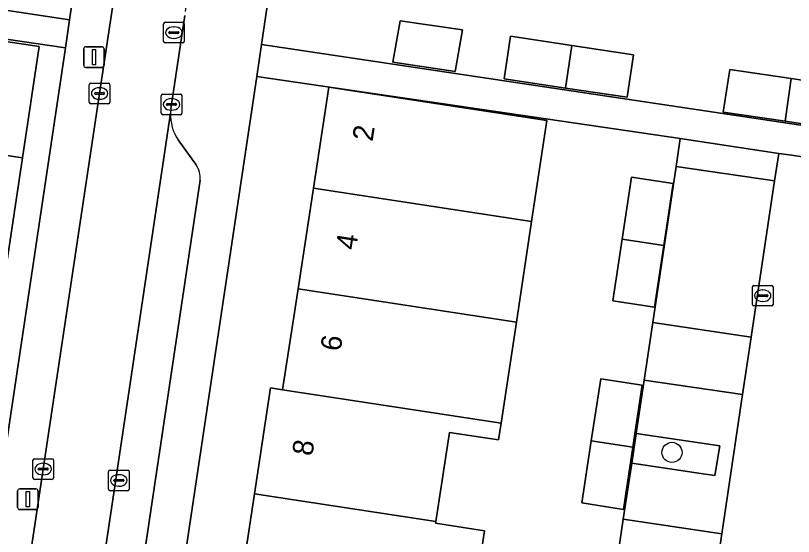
# Model space of a CAD drawing. Extents: x 164148 to 165261, y 382513 to 383432.
# Drawn here: x 164310.2 to 164347.95, y 382822.75 to 382848.02 of the extents above; entities that cross this region are included whole.
import ezdxf

# ---------------------------------------------------------------- set-up
doc = ezdxf.new("R2010")
doc.units = 0
for name, color, linetype in [('IMGEO_Boom', 7, 'Continuous'), ('IMGEO_Erf', 7, 'Continuous'), ('IMGEO_Groenvoorziening', 7, 'Continuous'), ('IMGEO_Kolk', 7, 'Continuous'), ('IMGEO_Lichtmast', 7, 'Continuous'), ('IMGEO_Pand', 7, 'Continuous'), ('IMGEO_Pand_nummerreeks', 7, 'Continuous'), ('IMGEO_Parkeervlak_open', 7, 'Continuous'), ('IMGEO_Rijbaan_lokaal_open', 7, 'Continuous'), ('IMGEO_Rioolput', 7, 'Continuous'), ('IMGEO_Voetpad_open', 7, 'Continuous')]:
    doc.layers.add(name, color=color, linetype=linetype)

msp = doc.modelspace()

# ---------------------------------------------------------------- linework, layer by layer
at = {"layer": 'IMGEO_Boom'}
msp.add_circle((164342.059, 382826.829), 0.489, dxfattribs=at)
at = {"layer": 'IMGEO_Erf'}
for points in [[(164315.881, 382868.253), (164315.414, 382868.927), (164260.822, 382877.103), (164260.194, 382876.574), (164257.168, 382856.277), (164287.898, 382851.603), (164312.82, 382847.812)], [(164380.889, 382859.124), (164325.776, 382867.343), (164325.126, 382866.898), (164322.133, 382846.618), (164350.25, 382842.417), (164378.331, 382838.195), (164381.369, 382858.602)], [(164312.617, 382846.453), (164292.449, 382849.423), (164292.087, 382847.018), (164291.688, 382844.368), (164291.474, 382842.945), (164291.038, 382840.051), (164290.538, 382836.727), (164289.415, 382829.267), (164288.932, 382826.06), (164287.807, 382818.59), (164287.325, 382815.39), (164286.852, 382812.248), (164286.634, 382810.8), (164286.198, 382807.902), (164285.91, 382805.985), (164306.097, 382802.914)], [(164295.742, 382810.175), (164296.551, 382815.581), (164297.361, 382820.987), (164298.17, 382826.393), (164298.979, 382831.798), (164299.789, 382837.204), (164300.598, 382842.61), (164301.407, 382848.016), (164311.351, 382846.529), (164310.54, 382841.122), (164309.73, 382835.716), (164308.919, 382830.31), (164308.108, 382824.905), (164307.298, 382819.499), (164306.487, 382814.093), (164305.677, 382808.688), (164304.859, 382803.235), (164294.933, 382804.769)], [(164331.884, 382847.33), (164331.535, 382845.31), (164328.504, 382845.765), (164328.874, 382847.776)], [(164337.206, 382846.568), (164340.195, 382846.118), (164339.885, 382844.057), (164336.896, 382844.506), (164333.907, 382844.956), (164334.217, 382847.017)], [(164350.836, 382844.524), (164350.517, 382842.454), (164347.545, 382842.897), (164344.545, 382843.344), (164344.866, 382845.407), (164347.851, 382844.966)], [(164339.185, 382834.177), (164339.639, 382837.178), (164340.095, 382840.186), (164342.122, 382839.869), (164341.664, 382836.869), (164341.205, 382833.868)], [(164340.618, 382830.085), (164340.165, 382827.081), (164339.709, 382824.062), (164337.69, 382824.381), (164338.145, 382827.387), (164338.599, 382830.392)]]:
    msp.add_lwpolyline(points, close=True, dxfattribs=at)
for points in [[(164336.319, 382801.003), (164336.717, 382803.665), (164337.854, 382811.264), (164338.195, 382813.542), (164339.299, 382820.92), (164339.698, 382823.586), (164340.106, 382826.312), (164340.321, 382827.745), (164340.709, 382830.337), (164341.126, 382833.13), (164342.26, 382840.703), (164342.463, 382842.062), (164321.904, 382845.071), (164308.618, 382756.371)], [(164321.014, 382819.693), (164321.797, 382824.824), (164322.58, 382829.954), (164323.163, 382829.865), (164323.91, 382834.759), (164324.656, 382839.654), (164325.403, 382844.548), (164335.987, 382842.933), (164335.246, 382838.038), (164334.505, 382833.143), (164333.764, 382828.247), (164333.642, 382827.438), (164331.262, 382827.801), (164330.603, 382823.48), (164330.589, 382823.386), (164332.963, 382823.024), (164332.195, 382817.987)]]:
    msp.add_lwpolyline(points, dxfattribs=at)
at = {"layer": 'IMGEO_Groenvoorziening'}
msp.add_lwpolyline([(164340.321, 382827.745), (164340.106, 382826.312), (164343.459, 382825.804), (164344.145, 382825.7), (164344.375, 382827.141)], close=True, dxfattribs=at)
at = {"layer": 'IMGEO_Kolk'}
for p, q in [((164313.777, 382843.818), (164313.777, 382844.67)), ((164313.852, 382844.744), (164314.704, 382844.744)), ((164314.778, 382844.67), (164314.778, 382843.818)), ((164314.036, 382844.238), (164314.036, 382844.25)), ((164314.079, 382844.287), (164314.477, 382844.287)), ((164314.265, 382844.524), (164314.29, 382844.524)), ((164314.52, 382844.25), (164314.52, 382844.238)), ((164314.474, 382844.201), (164314.076, 382844.201)), ((164314.288, 382843.964), (164314.263, 382843.964)), ((164317.27, 382843.288), (164317.27, 382844.14)), ((164317.345, 382844.214), (164318.197, 382844.214)), ((164317.758, 382843.994), (164317.783, 382843.994)), ((164318.271, 382844.14), (164318.271, 382843.288)), ((164314.704, 382843.744), (164313.852, 382843.744)), ((164317.529, 382843.708), (164317.529, 382843.72)), ((164317.967, 382843.671), (164317.569, 382843.671)), ((164317.572, 382843.757), (164317.97, 382843.757)), ((164318.013, 382843.72), (164318.013, 382843.708)), ((164318.197, 382843.214), (164317.345, 382843.214)), ((164317.781, 382843.434), (164317.756, 382843.434)), ((164345.962, 382834.006), (164345.962, 382834.858)), ((164346.037, 382834.932), (164346.889, 382834.932)), ((164346.963, 382834.858), (164346.963, 382834.006)), ((164346.221, 382834.426), (164346.221, 382834.438)), ((164346.264, 382834.475), (164346.662, 382834.475)), ((164346.45, 382834.712), (164346.475, 382834.712)), ((164346.705, 382834.438), (164346.705, 382834.426)), ((164346.659, 382834.389), (164346.261, 382834.389)), ((164346.473, 382834.152), (164346.448, 382834.152)), ((164346.889, 382833.932), (164346.037, 382833.932)), ((164311.115, 382826.519), (164311.967, 382826.519)), ((164311.04, 382825.593), (164311.04, 382826.445)), ((164311.528, 382826.299), (164311.553, 382826.299)), ((164312.041, 382826.445), (164312.041, 382825.593)), ((164311.299, 382826.013), (164311.299, 382826.025)), ((164311.737, 382825.976), (164311.339, 382825.976)), ((164311.342, 382826.062), (164311.74, 382826.062)), ((164311.551, 382825.739), (164311.526, 382825.739)), ((164311.783, 382826.025), (164311.783, 382826.013)), ((164314.71, 382825.041), (164314.71, 382825.893)), ((164314.785, 382825.967), (164315.637, 382825.967)), ((164315.198, 382825.747), (164315.223, 382825.747)), ((164315.711, 382825.893), (164315.711, 382825.041)), ((164311.967, 382825.519), (164311.115, 382825.519)), ((164314.969, 382825.461), (164314.969, 382825.473)), ((164315.407, 382825.424), (164315.009, 382825.424)), ((164315.012, 382825.51), (164315.41, 382825.51)), ((164315.453, 382825.473), (164315.453, 382825.461)), ((164315.221, 382825.187), (164315.196, 382825.187)), ((164315.637, 382824.967), (164314.785, 382824.967))]:
    msp.add_line(p, q, dxfattribs=at)
for points in [[(164313.777, 382843.818), (164313.777, 382844.67)], [(164313.852, 382844.744), (164314.704, 382844.744)], [(164314.778, 382844.67), (164314.778, 382843.818)], [(164317.27, 382843.288), (164317.27, 382844.14)], [(164317.345, 382844.214), (164318.197, 382844.214)], [(164318.271, 382844.14), (164318.271, 382843.288)], [(164314.704, 382843.744), (164313.852, 382843.744)], [(164318.197, 382843.214), (164317.345, 382843.214)], [(164345.962, 382834.006), (164345.962, 382834.858)], [(164346.037, 382834.932), (164346.889, 382834.932)], [(164346.963, 382834.858), (164346.963, 382834.006)], [(164346.889, 382833.932), (164346.037, 382833.932)], [(164311.115, 382826.519), (164311.967, 382826.519)], [(164311.04, 382825.593), (164311.04, 382826.445)], [(164312.041, 382826.445), (164312.041, 382825.593)], [(164314.71, 382825.041), (164314.71, 382825.893)], [(164314.785, 382825.967), (164315.637, 382825.967)], [(164315.711, 382825.893), (164315.711, 382825.041)], [(164311.967, 382825.519), (164311.115, 382825.519)], [(164315.637, 382824.967), (164314.785, 382824.967)]]:
    msp.add_lwpolyline(points, dxfattribs=at)
for centre, radius, start, end in [((164313.854, 382844.668), 0.0765, 91.552, 178.448), ((164313.854, 382844.668), 0.0765, 91.552, 178.448), ((164314.702, 382844.668), 0.0765, 1.552, 88.448), ((164314.702, 382844.668), 0.0765, 1.552, 88.448), ((164314.076, 382844.247), 0.0403, 85.8775, 175.7526), ((164314.073, 382844.237), 0.0366, 178.938, 274.7102), ((164314.477, 382844.244), 0.043, 264.8664, 352.4533), ((164314.481, 382844.249), 0.0386, 1.7309, 96.639), ((164317.347, 382844.138), 0.0765, 91.552, 178.448), ((164317.347, 382844.138), 0.0765, 91.552, 178.448), ((164318.195, 382844.138), 0.0765, 1.552, 88.448), ((164318.195, 382844.138), 0.0765, 1.552, 88.448), ((164313.854, 382843.82), 0.0765, 181.552, 268.448), ((164313.854, 382843.82), 0.0765, 181.552, 268.448), ((164314.702, 382843.82), 0.0765, 271.552, 358.448), ((164314.702, 382843.82), 0.0765, 271.552, 358.448), ((164317.569, 382843.717), 0.0403, 85.8775, 175.7526), ((164317.566, 382843.707), 0.0366, 178.938, 274.7102), ((164317.97, 382843.714), 0.043, 264.8664, 352.4533), ((164317.974, 382843.719), 0.0386, 1.7309, 96.639), ((164317.347, 382843.29), 0.0765, 181.552, 268.448), ((164317.347, 382843.29), 0.0765, 181.552, 268.448), ((164318.195, 382843.29), 0.0765, 271.552, 358.448), ((164318.195, 382843.29), 0.0765, 271.552, 358.448), ((164346.039, 382834.856), 0.0765, 91.552, 178.448), ((164346.039, 382834.856), 0.0765, 91.552, 178.448), ((164346.887, 382834.856), 0.0765, 1.552, 88.448), ((164346.887, 382834.856), 0.0765, 1.552, 88.448), ((164346.261, 382834.435), 0.0403, 85.8775, 175.7526), ((164346.258, 382834.425), 0.0366, 178.938, 274.7102), ((164346.662, 382834.432), 0.043, 264.8664, 352.4533), ((164346.666, 382834.437), 0.0386, 1.7309, 96.639), ((164346.039, 382834.008), 0.0765, 181.552, 268.448), ((164346.039, 382834.008), 0.0765, 181.552, 268.448), ((164346.887, 382834.008), 0.0765, 271.552, 358.448), ((164346.887, 382834.008), 0.0765, 271.552, 358.448), ((164311.117, 382826.443), 0.0765, 91.552, 178.448), ((164311.117, 382826.443), 0.0765, 91.552, 178.448), ((164311.965, 382826.443), 0.0765, 1.552, 88.448), ((164311.965, 382826.443), 0.0765, 1.552, 88.448), ((164311.339, 382826.022), 0.0403, 85.8775, 175.7526), ((164311.336, 382826.012), 0.0366, 178.938, 274.7102), ((164311.74, 382826.019), 0.043, 264.8664, 352.4533), ((164311.744, 382826.024), 0.0386, 1.7309, 96.639), ((164314.787, 382825.891), 0.0765, 91.552, 178.448), ((164314.787, 382825.891), 0.0765, 91.552, 178.448), ((164315.635, 382825.891), 0.0765, 1.552, 88.448), ((164315.635, 382825.891), 0.0765, 1.552, 88.448), ((164311.117, 382825.595), 0.0765, 181.552, 268.448), ((164311.117, 382825.595), 0.0765, 181.552, 268.448), ((164311.965, 382825.595), 0.0765, 271.552, 358.448), ((164311.965, 382825.595), 0.0765, 271.552, 358.448), ((164315.009, 382825.47), 0.0403, 85.8775, 175.7526), ((164315.006, 382825.46), 0.0366, 178.938, 274.7102), ((164315.41, 382825.467), 0.043, 264.8664, 352.4533), ((164315.414, 382825.472), 0.0386, 1.7309, 96.639), ((164314.787, 382825.043), 0.0765, 181.552, 268.448), ((164314.787, 382825.043), 0.0765, 181.552, 268.448), ((164315.635, 382825.043), 0.0765, 271.552, 358.448), ((164315.635, 382825.043), 0.0765, 271.552, 358.448)]:
    msp.add_arc(centre, radius, start, end, dxfattribs=at)
for centre, major_axis, ratio, start_param, end_param in [((164314.264, 382844.244), (-0.387, 0.002), 0.722429, 4.712389, 7.853982), ((164314.289, 382844.244), (-0.39, 0.002), 0.717154, 1.570796, 4.712389), ((164317.757, 382843.714), (-0.387, 0.002), 0.722429, 4.712389, 7.853982), ((164317.782, 382843.714), (-0.39, 0.002), 0.717154, 1.570796, 4.712389), ((164346.449, 382834.432), (-0.387, 0.002), 0.722429, 4.712389, 7.853982), ((164346.474, 382834.432), (-0.39, 0.002), 0.717154, 1.570796, 4.712389), ((164311.527, 382826.019), (-0.387, 0.002), 0.722429, 4.712389, 7.853982), ((164311.552, 382826.019), (-0.39, 0.002), 0.717154, 1.570796, 4.712389), ((164315.197, 382825.467), (-0.387, 0.002), 0.722429, 4.712389, 7.853982), ((164315.222, 382825.467), (-0.39, 0.002), 0.717154, 1.570796, 4.712389)]:
    msp.add_ellipse(centre, major_axis=major_axis, ratio=ratio, start_param=start_param, end_param=end_param, dxfattribs=at)
at = {"layer": 'IMGEO_Lichtmast'}
for p, q in [((164313.607, 382846.51), (164314.397, 382846.51)), ((164314.397, 382846.51), (164313.607, 382846.51)), ((164313.507, 382845.61), (164313.507, 382846.41)), ((164313.507, 382846.41), (164313.507, 382845.61)), ((164314.497, 382846.41), (164314.497, 382845.61)), ((164314.497, 382845.61), (164314.497, 382846.41)), ((164314.397, 382845.51), (164313.607, 382845.51)), ((164313.607, 382845.51), (164314.397, 382845.51)), ((164310.401, 382825.056), (164311.191, 382825.056)), ((164311.191, 382825.056), (164310.401, 382825.056)), ((164310.301, 382824.156), (164310.301, 382824.956)), ((164310.301, 382824.956), (164310.301, 382824.156)), ((164311.291, 382824.956), (164311.291, 382824.156)), ((164311.291, 382824.156), (164311.291, 382824.956)), ((164311.191, 382824.056), (164310.401, 382824.056)), ((164310.401, 382824.056), (164311.191, 382824.056))]:
    msp.add_line(p, q, dxfattribs=at)
for points in [[(164313.927, 382846.385), (164314.077, 382846.385), (164314.077, 382845.635), (164313.927, 382845.635), (164313.927, 382846.385)], [(164310.721, 382824.931), (164310.871, 382824.931), (164310.871, 382824.181), (164310.721, 382824.181), (164310.721, 382824.931)]]:
    msp.add_lwpolyline(points, dxfattribs=at)
for centre, start, end in [((164313.607, 382846.41), 90, 180), ((164313.607, 382846.41), 90, 180), ((164314.397, 382846.41), 0, 90), ((164314.397, 382846.41), 360, 90), ((164313.607, 382845.61), 180, 270), ((164313.607, 382845.61), 180, 270), ((164314.397, 382845.61), 270, 0), ((164314.397, 382845.61), 270, 0), ((164310.401, 382824.956), 90, 180), ((164310.401, 382824.956), 90, 180), ((164311.191, 382824.956), 0, 90), ((164311.191, 382824.956), 360, 90), ((164310.401, 382824.156), 180, 270), ((164310.401, 382824.156), 180, 270), ((164311.191, 382824.156), 270, 0), ((164311.191, 382824.156), 270, 0)]:
    msp.add_arc(centre, 0.1, start, end, dxfattribs=at)
at = {"layer": 'IMGEO_Pand'}
for points in [[(164301.407, 382848.016), (164300.598, 382842.61), (164310.54, 382841.122), (164311.351, 382846.529)], [(164331.884, 382847.33), (164328.874, 382847.776), (164328.504, 382845.765), (164331.535, 382845.31)], [(164337.206, 382846.568), (164334.217, 382847.017), (164333.907, 382844.956), (164336.896, 382844.506)], [(164340.195, 382846.118), (164337.206, 382846.568), (164336.896, 382844.506), (164339.885, 382844.057)], [(164347.851, 382844.966), (164344.866, 382845.407), (164344.545, 382843.344), (164347.545, 382842.897)], [(164350.836, 382844.524), (164347.851, 382844.966), (164347.545, 382842.897), (164350.517, 382842.454)], [(164335.987, 382842.933), (164325.403, 382844.548), (164324.656, 382839.654), (164335.246, 382838.038)], [(164310.54, 382841.122), (164300.598, 382842.61), (164299.789, 382837.204), (164309.73, 382835.716)], [(164342.122, 382839.869), (164340.095, 382840.186), (164339.639, 382837.178), (164341.664, 382836.869)], [(164335.246, 382838.038), (164324.656, 382839.654), (164323.91, 382834.759), (164334.505, 382833.143)], [(164341.664, 382836.869), (164339.639, 382837.178), (164339.185, 382834.177), (164341.205, 382833.868)], [(164334.505, 382833.143), (164323.91, 382834.759), (164323.163, 382829.865), (164333.764, 382828.247)], [(164338.599, 382830.392), (164338.145, 382827.387), (164340.165, 382827.081), (164340.618, 382830.085)], [(164331.262, 382827.801), (164333.642, 382827.438), (164333.764, 382828.247), (164323.163, 382829.865), (164322.58, 382829.954), (164321.797, 382824.824), (164330.603, 382823.48)], [(164340.165, 382827.081), (164338.145, 382827.387), (164337.69, 382824.381), (164339.709, 382824.062)], [(164332.963, 382823.024), (164330.589, 382823.386), (164330.603, 382823.48), (164321.797, 382824.824), (164321.014, 382819.693), (164321.607, 382819.602), (164332.195, 382817.987)]]:
    msp.add_lwpolyline(points, close=True, dxfattribs=at)
at = {"layer": 'IMGEO_Parkeervlak_open'}
for points in [[(164317.721, 382843.296), (164305.588, 382762.12)], [(164318.963, 382840.775), (164318.093, 382841.994)], [(164307.907, 382764.872), (164319.154, 382840.039)]]:
    msp.add_lwpolyline(points, dxfattribs=at)
for points in [[(164347.039, 382839.997), (164342.26, 382840.703), (164341.126, 382833.13), (164345.904, 382832.423)], [(164345.486, 382829.632), (164340.709, 382830.337), (164340.321, 382827.745), (164344.375, 382827.141), (164344.145, 382825.7), (164343.459, 382825.804), (164340.106, 382826.312), (164339.698, 382823.586), (164344.474, 382822.879)]]:
    msp.add_lwpolyline(points, close=True, dxfattribs=at)
for centre, radius, start, end in [((164319.868, 382843.205), 2.149, 177.5828, 214.308), ((164318.13, 382840.166), 1.032, 352.9241, 36.1718)]:
    msp.add_arc(centre, radius, start, end, dxfattribs=at)
at = {"layer": 'IMGEO_Rijbaan_lokaal_open'}
for points in [[(164318.45, 382848.222), (164320.963, 382865.023), (164320.969, 382865.121), (164317.478, 382865.636), (164317.049, 382862.672), (164314.278, 382844.244), (164311.541, 382826.019), (164308.94, 382808.745), (164306.009, 382789.028), (164302.972, 382768.762), (164301.88, 382761.702), (164305.445, 382761.166), (164305.559, 382761.978), (164305.588, 382762.12), (164317.721, 382843.296)], [(164317.74, 382843.507), (164317.771, 382843.714), (164318.416, 382848.033)], [(164346.706, 382799.875), (164347.108, 382802.559), (164348.119, 382809.31), (164348.538, 382812.111), (164349.669, 382819.657), (164349.993, 382821.825), (164351.128, 382829.402), (164351.515, 382831.984), (164352.523, 382838.717), (164352.791, 382840.504), (164352.276, 382840.585), (164347.755, 382841.26), (164347.238, 382841.326), (164347.039, 382839.997), (164345.904, 382832.423), (164345.486, 382829.632), (164344.474, 382822.879), (164344.073, 382820.206), (164342.967, 382812.827), (164342.629, 382810.568), (164341.49, 382802.969), (164341.089, 382800.293)]]:
    msp.add_lwpolyline(points, dxfattribs=at)
msp.add_arc((164319.934, 382843.203), 2.215, 172.1129, 177.5961, dxfattribs=at)
at = {"layer": 'IMGEO_Rioolput'}
for p, q in [((164317.459, 382847.699), (164318.311, 382847.699)), ((164317.384, 382846.773), (164317.384, 382847.625)), ((164317.872, 382847.479), (164317.897, 382847.479)), ((164318.385, 382847.625), (164318.385, 382846.773)), ((164317.643, 382847.193), (164317.643, 382847.205)), ((164318.081, 382847.156), (164317.683, 382847.156)), ((164317.686, 382847.242), (164318.084, 382847.242)), ((164317.895, 382846.919), (164317.87, 382846.919)), ((164318.127, 382847.205), (164318.127, 382847.193)), ((164318.311, 382846.699), (164317.459, 382846.699))]:
    msp.add_line(p, q, dxfattribs=at)
for points in [[(164317.459, 382847.699), (164318.311, 382847.699)], [(164317.384, 382846.773), (164317.384, 382847.625)], [(164318.385, 382847.625), (164318.385, 382846.773)], [(164318.311, 382846.699), (164317.459, 382846.699)]]:
    msp.add_lwpolyline(points, dxfattribs=at)
for centre, radius, start, end in [((164317.461, 382847.623), 0.0765, 91.552, 178.448), ((164317.461, 382847.623), 0.0765, 91.552, 178.448), ((164318.309, 382847.623), 0.0765, 1.552, 88.448), ((164318.309, 382847.623), 0.0765, 1.552, 88.448), ((164317.683, 382847.202), 0.0403, 85.8775, 175.7526), ((164317.68, 382847.192), 0.0366, 178.938, 274.7102), ((164318.084, 382847.199), 0.043, 264.8664, 352.4533), ((164318.088, 382847.204), 0.0386, 1.7309, 96.639), ((164317.461, 382846.775), 0.0765, 181.552, 268.448), ((164317.461, 382846.775), 0.0765, 181.552, 268.448), ((164318.309, 382846.775), 0.0765, 271.552, 358.448), ((164318.309, 382846.775), 0.0765, 271.552, 358.448)]:
    msp.add_arc(centre, radius, start, end, dxfattribs=at)
for centre, major_axis, ratio, start_param, end_param in [((164317.871, 382847.199), (-0.387, 0.002), 0.722429, 4.712389, 7.853982), ((164317.896, 382847.199), (-0.39, 0.002), 0.717154, 1.570796, 4.712389)]:
    msp.add_ellipse(centre, major_axis=major_axis, ratio=ratio, start_param=start_param, end_param=end_param, dxfattribs=at)
at = {"layer": 'IMGEO_Voetpad_open'}
for points in [[(164317.059, 382871.117), (164315.414, 382868.927), (164315.881, 382868.253), (164312.82, 382847.812), (164312.617, 382846.453), (164306.097, 382802.914), (164305.84, 382801.2), (164299.332, 382757.735), (164299.346, 382756.115)], [(164322.133, 382846.618), (164325.126, 382866.898), (164325.776, 382867.343), (164323.888, 382870.662)], [(164308.94, 382808.745), (164311.541, 382826.019), (164314.278, 382844.244), (164317.049, 382862.672), (164317.478, 382865.636), (164317.658, 382866.876)], [(164318.416, 382848.033), (164317.771, 382843.714), (164317.74, 382843.507)], [(164306.314, 382754.511), (164308.618, 382756.371), (164321.904, 382845.071), (164322.133, 382846.618)], [(164318.093, 382841.994), (164318.963, 382840.775)], [(164319.154, 382840.039), (164307.907, 382764.872)]]:
    msp.add_lwpolyline(points, dxfattribs=at)
for points in [[(164287.898, 382851.603), (164257.168, 382856.277), (164256.94, 382854.753), (164277.152, 382851.711), (164281.938, 382850.991), (164287.676, 382850.126), (164292.449, 382849.423), (164312.617, 382846.453), (164312.82, 382847.812)], [(164350.25, 382842.417), (164322.133, 382846.618), (164321.904, 382845.071), (164342.463, 382842.062), (164347.238, 382841.326), (164347.755, 382841.26), (164352.276, 382840.585), (164352.791, 382840.504), (164357.562, 382839.799), (164378.11, 382836.71), (164378.331, 382838.195)], [(164347.238, 382841.326), (164342.463, 382842.062), (164342.26, 382840.703), (164347.039, 382839.997)], [(164345.904, 382832.423), (164341.126, 382833.13), (164340.709, 382830.337), (164345.486, 382829.632)], [(164344.474, 382822.879), (164339.698, 382823.586), (164339.299, 382820.92), (164344.073, 382820.206)]]:
    msp.add_lwpolyline(points, close=True, dxfattribs=at)
for centre, radius, start, end in [((164319.934, 382843.203), 2.215, 172.1129, 177.5961), ((164319.868, 382843.205), 2.149, 177.5828, 214.308), ((164318.13, 382840.166), 1.032, 352.9241, 36.1718)]:
    msp.add_arc(centre, radius, start, end, dxfattribs=at)

# ---------------------------------------------------------------- texts
at = {"layer": 'IMGEO_Pand_nummerreeks'}
for s, rotation, p in [('2', 81.1251, (164327.525, 382841.886)), ('4', 81.1366, (164326.721, 382836.616)), ('6', 81.1251, (164325.971, 382831.7)), ('8', 81.1251, (164324.599, 382826.62))]:
    msp.add_text(s, height=1, rotation=rotation, dxfattribs=at).set_placement(p)

doc.saveas('drawing.dxf')
